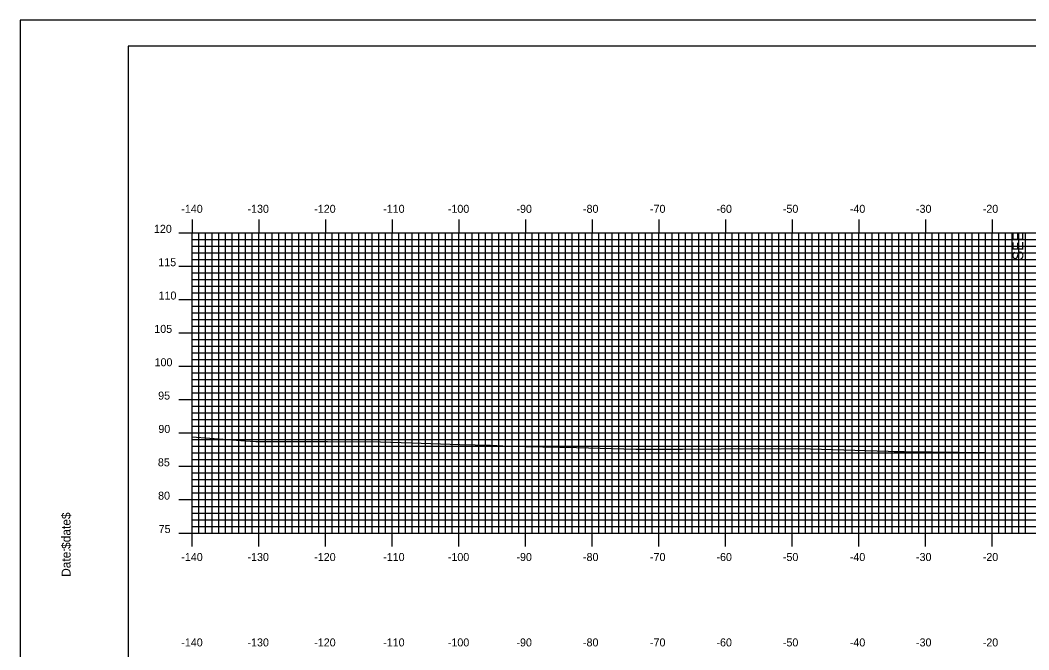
# Model space of a CAD drawing. Extents: x 855297 to 855640, y 364366 to 364586.
# Drawn here: x 855297 to 855448.3, y 364491.3 to 364585.7 of the extents above; entities that cross this region are included whole.
import ezdxf

# ---------------------------------------------------------------- set-up
doc = ezdxf.new("R2010")
doc.units = 0
for name, color, linetype in [('ANNOTATION', 7, 'Continuous'), ('BORDER', 7, 'Continuous'), ('H_V ANNOTATION', 7, 'Continuous'), ('MAJOR', 7, 'Continuous'), ('MINOR', 7, 'Continuous'), ('PLOT BOUNDARY', 7, 'Continuous'), ('S_Roadway_Centerline', 7, 'Continuous')]:
    doc.layers.add(name, color=color, linetype=linetype)

msp = doc.modelspace()

# ---------------------------------------------------------------- linework, layer by layer
at = {"layer": 'BORDER'}
msp.add_lwpolyline([(855313.17, 364371.79), (855633.17, 364371.79), (855633.17, 364581.79), (855313.17, 364581.79)], close=True, dxfattribs=at)
at = {"layer": 'MAJOR'}
for p, q in [((855322.77, 364555.79), (855322.77, 364553.79)), ((855332.77, 364555.79), (855332.77, 364553.79)), ((855342.77, 364555.79), (855342.77, 364553.79)), ((855352.77, 364555.79), (855352.77, 364553.79)), ((855362.77, 364555.79), (855362.77, 364553.79)), ((855372.77, 364555.79), (855372.77, 364553.79)), ((855382.77, 364555.79), (855382.77, 364553.79)), ((855392.77, 364555.79), (855392.77, 364553.79)), ((855402.77, 364555.79), (855402.77, 364553.79)), ((855412.77, 364555.79), (855412.77, 364553.79)), ((855422.77, 364555.79), (855422.77, 364553.79)), ((855432.77, 364555.79), (855432.77, 364553.79)), ((855442.77, 364555.79), (855442.77, 364553.79)), ((855320.77, 364553.79), (855322.77, 364553.79)), ((855322.77, 364553.79), (855602.77, 364553.79)), ((855322.77, 364508.79), (855322.77, 364553.79)), ((855322.77, 364508.79), (855322.77, 364553.79)), ((855322.77, 364553.79), (855602.77, 364553.79)), ((855332.77, 364508.79), (855332.77, 364553.79)), ((855342.77, 364508.79), (855342.77, 364553.79)), ((855352.77, 364508.79), (855352.77, 364553.79)), ((855362.77, 364508.79), (855362.77, 364553.79)), ((855372.77, 364508.79), (855372.77, 364553.79)), ((855382.77, 364508.79), (855382.77, 364553.79)), ((855392.77, 364508.79), (855392.77, 364553.79)), ((855402.77, 364508.79), (855402.77, 364553.79)), ((855412.77, 364508.79), (855412.77, 364553.79)), ((855422.77, 364508.79), (855422.77, 364553.79)), ((855432.77, 364508.79), (855432.77, 364553.79)), ((855442.77, 364508.79), (855442.77, 364553.79)), ((855320.77, 364548.79), (855322.77, 364548.79)), ((855322.77, 364548.79), (855602.77, 364548.79)), ((855320.77, 364543.79), (855322.77, 364543.79)), ((855322.77, 364543.79), (855602.77, 364543.79)), ((855320.77, 364538.79), (855322.77, 364538.79)), ((855322.77, 364538.79), (855602.77, 364538.79)), ((855320.77, 364533.79), (855322.77, 364533.79)), ((855322.77, 364533.79), (855602.77, 364533.79)), ((855320.77, 364528.79), (855322.77, 364528.79)), ((855322.77, 364528.79), (855602.77, 364528.79)), ((855320.77, 364523.79), (855322.77, 364523.79)), ((855322.77, 364523.79), (855602.77, 364523.79)), ((855320.77, 364518.79), (855322.77, 364518.79)), ((855322.77, 364518.79), (855602.77, 364518.79)), ((855320.77, 364513.79), (855322.77, 364513.79)), ((855322.77, 364513.79), (855602.77, 364513.79)), ((855320.77, 364508.79), (855322.77, 364508.79)), ((855322.77, 364508.79), (855602.77, 364508.79)), ((855322.77, 364508.79), (855602.77, 364508.79)), ((855322.77, 364506.78), (855322.77, 364508.79)), ((855332.77, 364506.78), (855332.77, 364508.79)), ((855342.77, 364506.78), (855342.77, 364508.79)), ((855352.77, 364506.78), (855352.77, 364508.79)), ((855362.77, 364506.78), (855362.77, 364508.79)), ((855372.77, 364506.78), (855372.77, 364508.79)), ((855382.77, 364506.78), (855382.77, 364508.79)), ((855392.77, 364506.78), (855392.77, 364508.79)), ((855402.77, 364506.78), (855402.77, 364508.79)), ((855412.77, 364506.78), (855412.77, 364508.79)), ((855422.77, 364506.78), (855422.77, 364508.79)), ((855432.77, 364506.78), (855432.77, 364508.79)), ((855442.77, 364506.78), (855442.77, 364508.79))]:
    msp.add_line(p, q, dxfattribs=at)
at = {"layer": 'MINOR'}
for p, q in [((855322.77, 364552.79), (855602.77, 364552.79)), ((855322.77, 364552.79), (855324.77, 364552.79)), ((855323.77, 364508.79), (855323.77, 364553.79)), ((855324.77, 364508.79), (855324.77, 364553.79)), ((855325.77, 364508.79), (855325.77, 364553.79)), ((855326.77, 364508.79), (855326.77, 364553.79)), ((855327.77, 364508.79), (855327.77, 364553.79)), ((855328.77, 364508.79), (855328.77, 364553.79)), ((855329.77, 364508.79), (855329.77, 364553.79)), ((855330.77, 364508.79), (855330.77, 364553.79)), ((855331.77, 364508.79), (855331.77, 364553.79)), ((855333.77, 364508.79), (855333.77, 364553.79)), ((855334.77, 364508.79), (855334.77, 364553.79)), ((855335.77, 364508.79), (855335.77, 364553.79)), ((855336.77, 364508.79), (855336.77, 364553.79)), ((855337.77, 364508.79), (855337.77, 364553.79)), ((855338.77, 364508.79), (855338.77, 364553.79)), ((855339.77, 364508.79), (855339.77, 364553.79)), ((855340.77, 364508.79), (855340.77, 364553.79)), ((855341.77, 364508.79), (855341.77, 364553.79)), ((855343.77, 364508.79), (855343.77, 364553.79)), ((855344.77, 364508.79), (855344.77, 364553.79)), ((855345.77, 364508.79), (855345.77, 364553.79)), ((855346.77, 364508.79), (855346.77, 364553.79)), ((855347.77, 364508.79), (855347.77, 364553.79)), ((855348.77, 364508.79), (855348.77, 364553.79)), ((855349.77, 364508.79), (855349.77, 364553.79)), ((855350.77, 364508.79), (855350.77, 364553.79)), ((855351.77, 364508.79), (855351.77, 364553.79)), ((855353.77, 364508.79), (855353.77, 364553.79)), ((855354.77, 364508.79), (855354.77, 364553.79)), ((855355.77, 364508.79), (855355.77, 364553.79)), ((855356.77, 364508.79), (855356.77, 364553.79)), ((855357.77, 364508.79), (855357.77, 364553.79)), ((855358.77, 364508.79), (855358.77, 364553.79)), ((855359.77, 364508.79), (855359.77, 364553.79)), ((855360.77, 364508.79), (855360.77, 364553.79)), ((855361.77, 364508.79), (855361.77, 364553.79)), ((855363.77, 364508.79), (855363.77, 364553.79)), ((855364.77, 364508.79), (855364.77, 364553.79)), ((855365.77, 364508.79), (855365.77, 364553.79)), ((855366.77, 364508.79), (855366.77, 364553.79)), ((855367.77, 364508.79), (855367.77, 364553.79)), ((855368.77, 364508.79), (855368.77, 364553.79)), ((855369.77, 364508.79), (855369.77, 364553.79)), ((855370.77, 364508.79), (855370.77, 364553.79)), ((855371.77, 364508.79), (855371.77, 364553.79)), ((855373.77, 364508.79), (855373.77, 364553.79)), ((855374.77, 364508.79), (855374.77, 364553.79)), ((855375.77, 364508.79), (855375.77, 364553.79)), ((855376.77, 364508.79), (855376.77, 364553.79)), ((855377.77, 364508.79), (855377.77, 364553.79)), ((855378.77, 364508.79), (855378.77, 364553.79)), ((855379.77, 364508.79), (855379.77, 364553.79)), ((855380.77, 364508.79), (855380.77, 364553.79)), ((855381.77, 364508.79), (855381.77, 364553.79)), ((855383.77, 364508.79), (855383.77, 364553.79)), ((855384.77, 364508.79), (855384.77, 364553.79)), ((855385.77, 364508.79), (855385.77, 364553.79)), ((855386.77, 364508.79), (855386.77, 364553.79)), ((855387.77, 364508.79), (855387.77, 364553.79)), ((855388.77, 364508.79), (855388.77, 364553.79)), ((855389.77, 364508.79), (855389.77, 364553.79)), ((855390.77, 364508.79), (855390.77, 364553.79)), ((855391.77, 364508.79), (855391.77, 364553.79)), ((855393.77, 364508.79), (855393.77, 364553.79)), ((855394.77, 364508.79), (855394.77, 364553.79)), ((855395.77, 364508.79), (855395.77, 364553.79)), ((855396.77, 364508.79), (855396.77, 364553.79)), ((855397.77, 364508.79), (855397.77, 364553.79)), ((855398.77, 364508.79), (855398.77, 364553.79)), ((855399.77, 364508.79), (855399.77, 364553.79)), ((855400.77, 364508.79), (855400.77, 364553.79)), ((855401.77, 364508.79), (855401.77, 364553.79)), ((855403.77, 364508.79), (855403.77, 364553.79)), ((855404.77, 364508.79), (855404.77, 364553.79)), ((855405.77, 364508.79), (855405.77, 364553.79)), ((855406.77, 364508.79), (855406.77, 364553.79)), ((855407.77, 364508.79), (855407.77, 364553.79)), ((855408.77, 364508.79), (855408.77, 364553.79)), ((855409.77, 364508.79), (855409.77, 364553.79)), ((855410.77, 364508.79), (855410.77, 364553.79)), ((855411.77, 364508.79), (855411.77, 364553.79)), ((855413.77, 364508.79), (855413.77, 364553.79)), ((855414.77, 364508.79), (855414.77, 364553.79)), ((855415.77, 364508.79), (855415.77, 364553.79)), ((855416.77, 364508.79), (855416.77, 364553.79)), ((855417.77, 364508.79), (855417.77, 364553.79)), ((855418.77, 364508.79), (855418.77, 364553.79)), ((855419.77, 364508.79), (855419.77, 364553.79)), ((855420.77, 364508.79), (855420.77, 364553.79)), ((855421.77, 364508.79), (855421.77, 364553.79)), ((855423.77, 364508.79), (855423.77, 364553.79)), ((855424.77, 364508.79), (855424.77, 364553.79)), ((855425.77, 364508.79), (855425.77, 364553.79)), ((855426.77, 364508.79), (855426.77, 364553.79)), ((855427.77, 364508.79), (855427.77, 364553.79)), ((855428.77, 364508.79), (855428.77, 364553.79)), ((855429.77, 364508.79), (855429.77, 364553.79)), ((855430.77, 364508.79), (855430.77, 364553.79)), ((855431.77, 364508.79), (855431.77, 364553.79)), ((855433.77, 364508.79), (855433.77, 364553.79)), ((855434.77, 364508.79), (855434.77, 364553.79)), ((855435.77, 364508.79), (855435.77, 364553.79)), ((855436.77, 364508.79), (855436.77, 364553.79)), ((855437.77, 364508.79), (855437.77, 364553.79)), ((855438.77, 364508.79), (855438.77, 364553.79)), ((855439.77, 364508.79), (855439.77, 364553.79)), ((855440.77, 364508.79), (855440.77, 364553.79)), ((855441.77, 364508.79), (855441.77, 364553.79)), ((855443.77, 364508.79), (855443.77, 364553.79)), ((855444.77, 364508.79), (855444.77, 364553.79)), ((855445.77, 364508.79), (855445.77, 364553.79)), ((855446.77, 364508.79), (855446.77, 364553.79)), ((855447.77, 364508.79), (855447.77, 364553.79)), ((855322.77, 364551.79), (855602.77, 364551.79)), ((855322.77, 364551.79), (855324.77, 364551.79)), ((855322.77, 364550.79), (855602.77, 364550.79)), ((855322.77, 364550.79), (855324.77, 364550.79)), ((855322.77, 364549.79), (855602.77, 364549.79)), ((855322.77, 364549.79), (855324.77, 364549.79)), ((855322.77, 364547.79), (855602.77, 364547.79)), ((855322.77, 364547.79), (855324.77, 364547.79)), ((855322.77, 364546.79), (855602.77, 364546.79)), ((855322.77, 364546.79), (855324.77, 364546.79)), ((855322.77, 364545.79), (855602.77, 364545.79)), ((855322.77, 364545.79), (855324.77, 364545.79)), ((855322.77, 364544.79), (855602.77, 364544.79)), ((855322.77, 364544.79), (855324.77, 364544.79)), ((855322.77, 364542.79), (855602.77, 364542.79)), ((855322.77, 364542.79), (855324.77, 364542.79)), ((855322.77, 364541.79), (855602.77, 364541.79)), ((855322.77, 364541.79), (855324.77, 364541.79)), ((855322.77, 364540.79), (855602.77, 364540.79)), ((855322.77, 364540.79), (855324.77, 364540.79)), ((855322.77, 364539.79), (855602.77, 364539.79)), ((855322.77, 364539.79), (855324.77, 364539.79)), ((855322.77, 364537.79), (855602.77, 364537.79)), ((855322.77, 364537.79), (855324.77, 364537.79)), ((855322.77, 364536.79), (855602.77, 364536.79)), ((855322.77, 364536.79), (855324.77, 364536.79)), ((855322.77, 364535.79), (855602.77, 364535.79)), ((855322.77, 364535.79), (855324.77, 364535.79)), ((855322.77, 364534.79), (855602.77, 364534.79)), ((855322.77, 364534.79), (855324.77, 364534.79)), ((855322.77, 364532.79), (855602.77, 364532.79)), ((855322.77, 364532.79), (855324.77, 364532.79)), ((855322.77, 364531.79), (855602.77, 364531.79)), ((855322.77, 364531.79), (855324.77, 364531.79)), ((855322.77, 364530.79), (855602.77, 364530.79)), ((855322.77, 364530.79), (855324.77, 364530.79)), ((855322.77, 364529.79), (855602.77, 364529.79)), ((855322.77, 364529.79), (855324.77, 364529.79)), ((855322.77, 364527.79), (855602.77, 364527.79)), ((855322.77, 364527.79), (855324.77, 364527.79)), ((855322.77, 364526.79), (855602.77, 364526.79)), ((855322.77, 364526.79), (855324.77, 364526.79)), ((855322.77, 364525.79), (855602.77, 364525.79)), ((855322.77, 364525.79), (855324.77, 364525.79)), ((855322.77, 364524.79), (855602.77, 364524.79)), ((855322.77, 364524.79), (855324.77, 364524.79)), ((855322.77, 364522.79), (855602.77, 364522.79)), ((855322.77, 364522.79), (855324.77, 364522.79)), ((855322.77, 364521.79), (855602.77, 364521.79)), ((855322.77, 364521.79), (855324.77, 364521.79)), ((855322.77, 364520.79), (855602.77, 364520.79)), ((855322.77, 364520.79), (855324.77, 364520.79)), ((855322.77, 364519.79), (855602.77, 364519.79)), ((855322.77, 364519.79), (855324.77, 364519.79)), ((855322.77, 364517.79), (855602.77, 364517.79)), ((855322.77, 364517.79), (855324.77, 364517.79)), ((855322.77, 364516.79), (855602.77, 364516.79)), ((855322.77, 364516.79), (855324.77, 364516.79)), ((855322.77, 364515.79), (855602.77, 364515.79)), ((855322.77, 364515.79), (855324.77, 364515.79)), ((855322.77, 364514.79), (855602.77, 364514.79)), ((855322.77, 364514.79), (855324.77, 364514.79)), ((855322.77, 364512.79), (855602.77, 364512.79)), ((855322.77, 364512.79), (855324.77, 364512.79)), ((855322.77, 364511.79), (855602.77, 364511.79)), ((855322.77, 364511.79), (855324.77, 364511.79)), ((855322.77, 364510.79), (855602.77, 364510.79)), ((855322.77, 364510.79), (855324.77, 364510.79)), ((855322.77, 364509.79), (855602.77, 364509.79)), ((855322.77, 364509.79), (855324.77, 364509.79))]:
    msp.add_line(p, q, dxfattribs=at)
at = {"layer": 'PLOT BOUNDARY'}
msp.add_lwpolyline([(855296.98, 364365.67), (855636.98, 364365.67), (855636.98, 364585.67), (855296.98, 364585.67)], close=True, dxfattribs=at)
at = {"layer": 'S_Roadway_Centerline'}
msp.add_lwpolyline([(855322.77, 364523.21), (855330.72, 364522.61), (855332.35, 364522.5), (855343.06, 364522.5), (855351.03, 364522.47), (855355.67, 364522.32), (855362.92, 364522.07), (855367.51, 364521.94), (855370.34, 364521.83), (855380.41, 364521.62), (855389.35, 364521.38), (855396.31, 364521.35), (855407.92, 364521.44), (855415.53, 364521.43), (855427.15, 364521.05), (855428.05, 364521.03), (855429.55, 364521), (855445.9, 364520.79), (855451.26, 364520.75)], dxfattribs=at)

# ---------------------------------------------------------------- texts
at = {"layer": 'ANNOTATION'}
msp.add_text('SEE', height=1.6, rotation=90, dxfattribs=at).set_placement((855447.43, 364549.67))
at = {"layer": 'BORDER'}
for s, p in [('$date$', (855304.54, 364506.4)), ('Date:', (855304.54, 364502.22))]:
    msp.add_text(s, height=1.339, rotation=90, dxfattribs=at).set_placement(p)
at = {"layer": 'H_V ANNOTATION'}
for s, p in [('-140', (855321.15, 364556.79)), ('-130', (855331.08, 364556.79)), ('-120', (855341.09, 364556.79)), ('-110', (855351.43, 364556.79)), ('-100', (855361.13, 364556.79)), ('-90', (855371.42, 364556.79)), ('-80', (855381.4, 364556.79)), ('-70', (855391.45, 364556.79)), ('-60', (855401.42, 364556.79)), ('-50', (855411.38, 364556.79)), ('-40', (855421.42, 364556.79)), ('-30', (855431.35, 364556.79)), ('-20', (855441.36, 364556.79)), ('120', (855317.05, 364553.79)), ('115', (855317.7, 364548.79)), ('110', (855317.74, 364543.79)), ('105', (855317.1, 364538.79)), ('100', (855317.14, 364533.79)), ('95', (855317.68, 364528.79)), ('90', (855317.71, 364523.79)), ('85', (855317.64, 364518.79)), ('80', (855317.67, 364513.79)), ('75', (855317.75, 364508.79)), ('-140', (855321.15, 364504.59)), ('-130', (855331.08, 364504.59)), ('-120', (855341.09, 364504.59)), ('-110', (855351.43, 364504.59)), ('-100', (855361.13, 364504.59)), ('-90', (855371.42, 364504.59)), ('-80', (855381.4, 364504.59)), ('-70', (855391.45, 364504.59)), ('-60', (855401.42, 364504.59)), ('-50', (855411.38, 364504.59)), ('-40', (855421.42, 364504.59)), ('-30', (855431.35, 364504.59)), ('-20', (855441.36, 364504.59)), ('-140', (855321.15, 364491.79)), ('-130', (855331.08, 364491.79)), ('-120', (855341.09, 364491.79)), ('-110', (855351.43, 364491.79)), ('-100', (855361.13, 364491.79)), ('-90', (855371.42, 364491.79)), ('-80', (855381.4, 364491.79)), ('-70', (855391.45, 364491.79)), ('-60', (855401.42, 364491.79)), ('-50', (855411.38, 364491.79)), ('-40', (855421.42, 364491.79)), ('-30', (855431.35, 364491.79)), ('-20', (855441.36, 364491.79))]:
    msp.add_text(s, height=1.2, dxfattribs=at).set_placement(p)
at = {"layer": 'MAJOR'}
msp.add_text('-', height=0.012, dxfattribs=at).set_placement((855322.76, 364508.79))

doc.saveas('drawing.dxf')
